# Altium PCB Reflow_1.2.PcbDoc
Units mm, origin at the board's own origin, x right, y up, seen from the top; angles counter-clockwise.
Board outline 49.5 x 49.5 mm, 2 copper layers (Top Layer, Bottom Layer); 51 components, 57 nets, 187 pads, 58 vias.
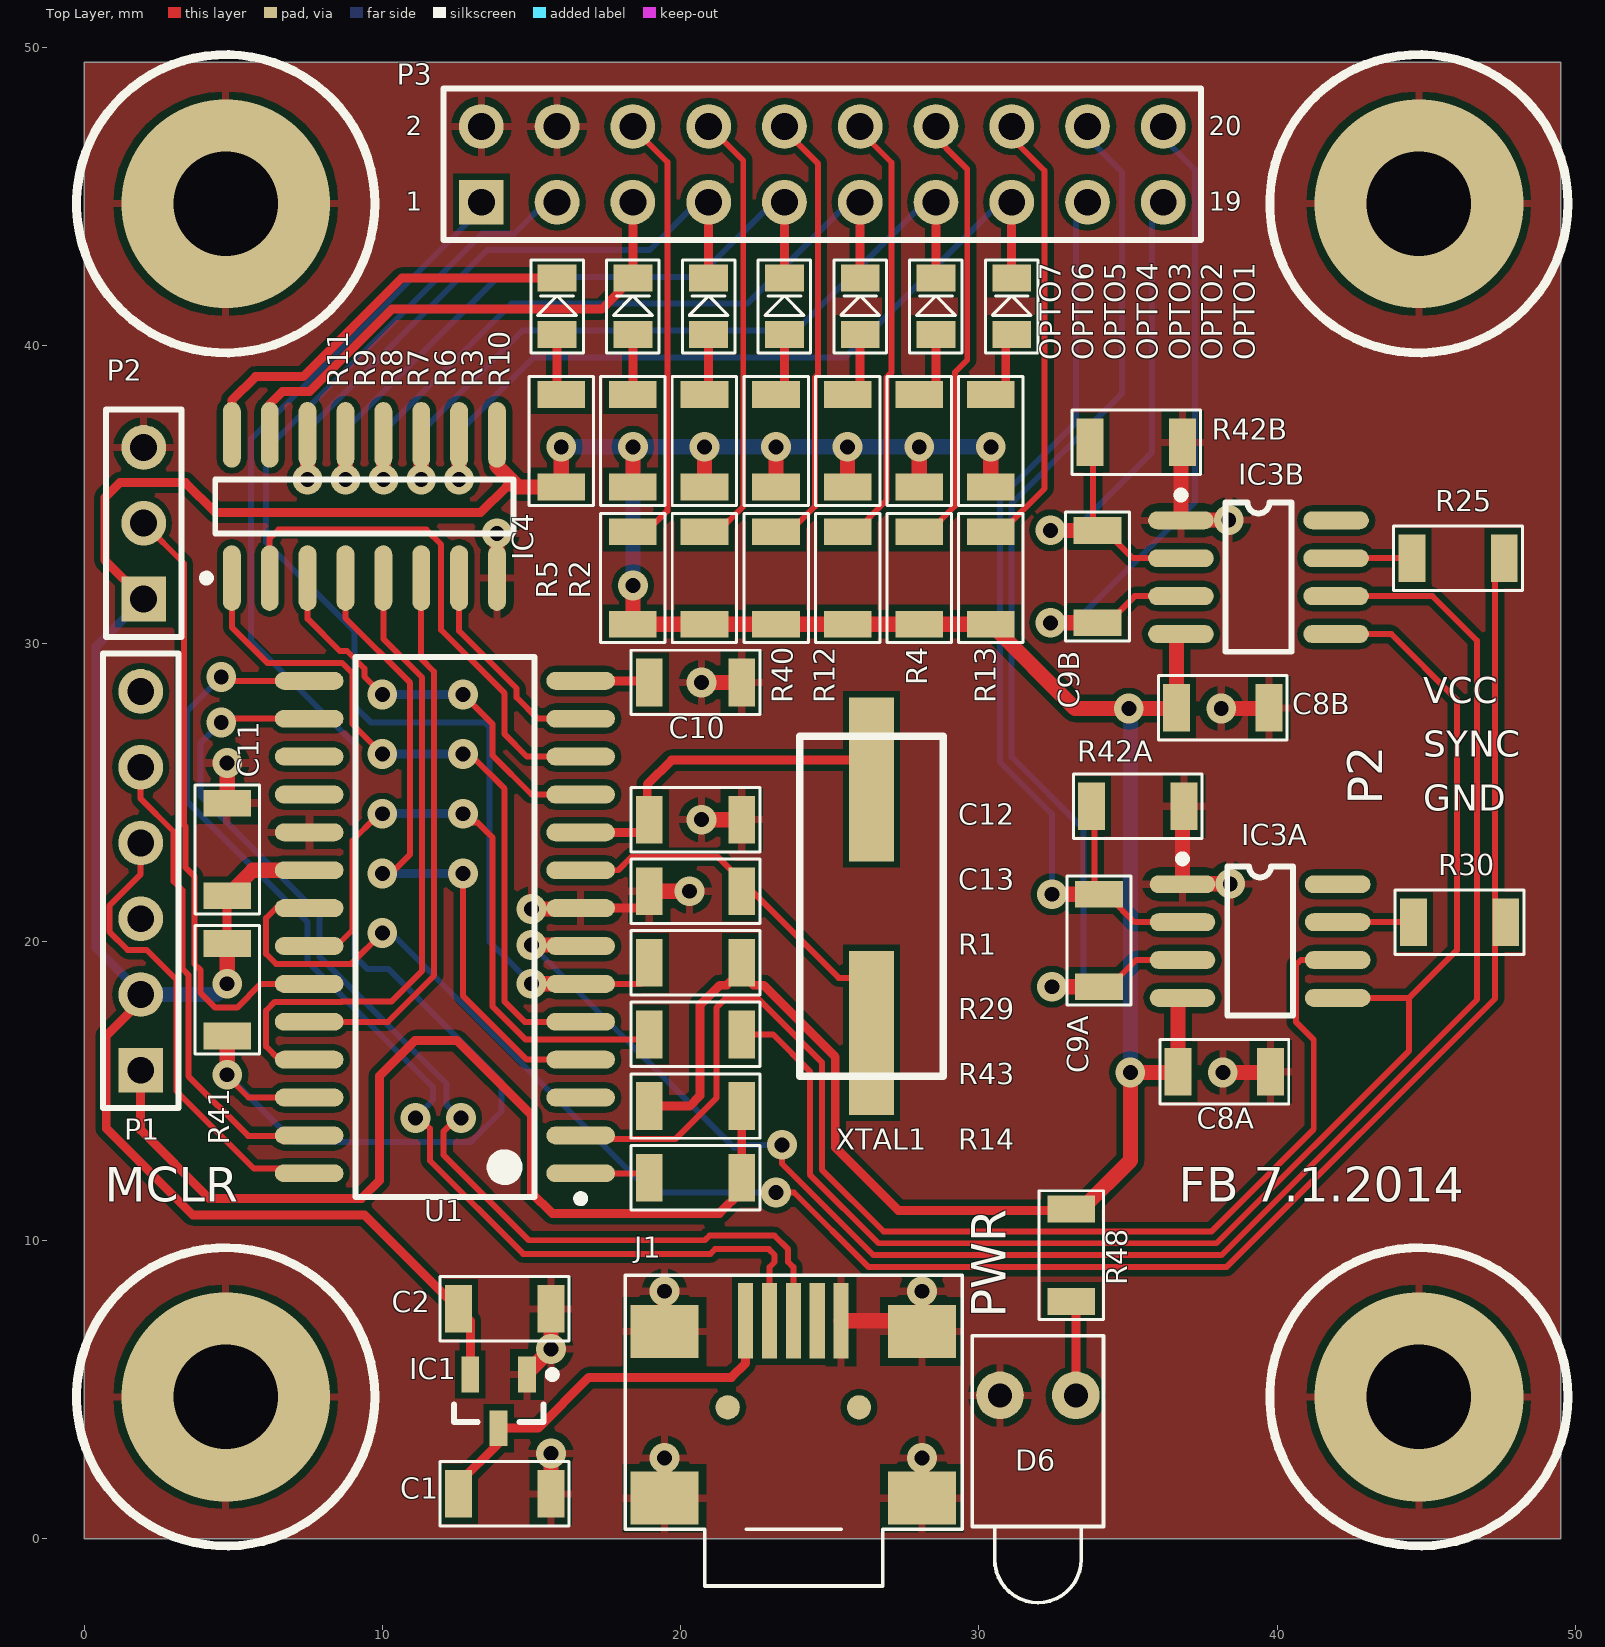
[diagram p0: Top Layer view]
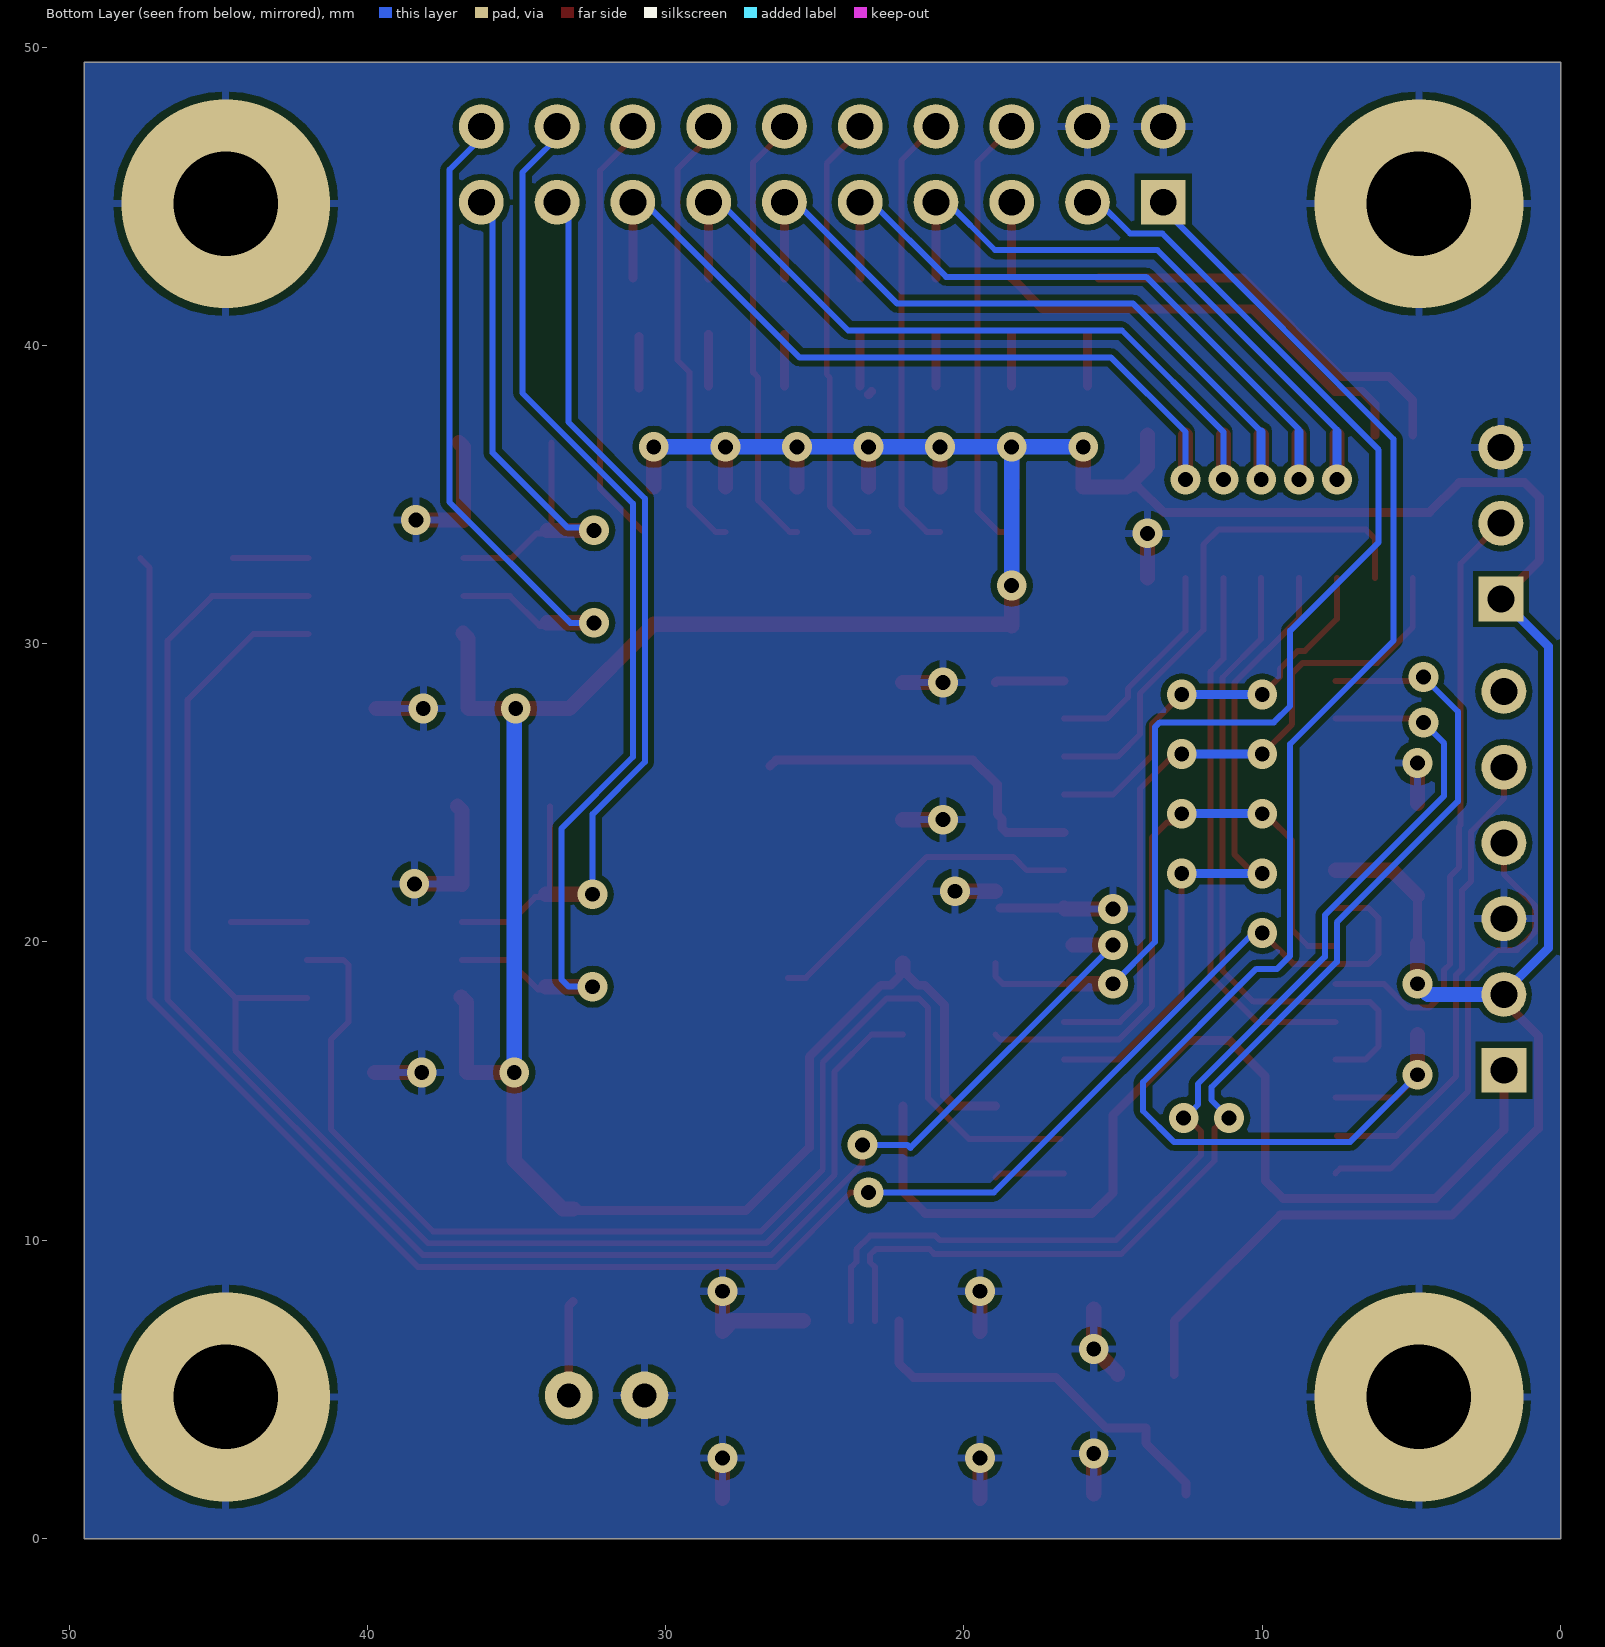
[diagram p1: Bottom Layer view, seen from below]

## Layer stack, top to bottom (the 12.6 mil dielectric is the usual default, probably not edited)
Top Solder: solder mask 0.0102, Solder Resist, Dk 3.5
Top Layer: signal copper 0.0356
Dielectric1: dielectric 0.32, FR-4, Dk 4.8
Bottom Layer: signal copper 0.0356
Bottom Solder: solder mask 0.0102, Solder Resist, Dk 3.5

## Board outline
0,0 0,49.5 49.5,49.5 49.5,0

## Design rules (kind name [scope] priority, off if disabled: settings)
Clearance [All] p1: gap=0.2
DiffPairsRouting [All] p1 off: maxlimit=0.254 minlimit=0.254 mostfreqgap=0.254 toplayer_minwidth=0.381 toplayer_maxwidth=0.381 toplayer_prefwidth=0.381 bottomlayer_minwidth=0.381 bottomlayer_maxwidth=0.381 bottomlayer_prefwidth=0.381 maxuncoupledlength=12.7
FabricationTestPointUsage [All] p1 off: valid=0 allowmultiple=FALSE
FabricationTestpoint [(IsPad And (OnTopLayer Or OnBottomLayer))] p1 off: side=3 testpointundercomponent=TRUE minsize=1.016 maxsize=2.54 preferedsize=1.524 minholesize=0 maxholesize=1.016 preferedholesize=0.813 testpointgrid=0.025 allowsidetop=TRUE allowsidebottom=TRUE usegrid=TRUE gridtolerance=0
FanoutControl Fanout_BGA [IsBGA] p1 off: bgadir=Out bgaviamode=Centered fanoutstyle=Auto fanoutdirection=Alternating viagrid=0.025 // Fanout_BGA (Default Rule)
FanoutControl Fanout_LCC [IsLCC] p2 off: bgadir=Out bgaviamode=Centered fanoutstyle=Auto fanoutdirection=Alternating viagrid=0.025 // Fanout_LCC (Default Rule)
FanoutControl Fanout_SOIC [IsSOIC] p3 off: bgadir=Out bgaviamode=Centered fanoutstyle=Auto fanoutdirection=Alternating viagrid=0.025 // Fanout_SOIC (Default Rule)
FanoutControl Fanout_Small [(CompPinCount < 5)] p4 off: bgadir=Out bgaviamode=Centered fanoutstyle=Auto fanoutdirection=OutThenIn viagrid=0.025 // Fanout_Small (Default Rule)
FanoutControl Fanout_Default [All] p5 off: bgadir=Out bgaviamode=Centered fanoutstyle=Auto fanoutdirection=Alternating viagrid=0.025 // Fanout_Default (Default Rule)
Height [All] p1 off: minheight=0 maxheight=25.4 prefheight=12.7
HoleSize [All] p1: absolutevalues=TRUE maxlimit=4.5 minlimit=0.025 maxpercent=80.000 minpercent=20.000
LayerPairs [All] p1 off: enforce=TRUE
MinimumSolderMaskSliver [All] p1 off: minsoldermaskwidth=0.254
PasteMaskExpansion [All] p1 off: expansion=0
PolygonConnect [All] p1: connectstyle=Relief reliefconductorwidth=0.254 reliefentries=4 polygonreliefangle="90 Angle" airgapwidth=0.254
RoomDefinition U_MAX66752 [InComponentClass('U_MAX66752')] p1: confinementstyle=ConfineIn formatcopy=TRUE lockcomponents=FALSE outline 46.026,38.825 30.975,38.825 30.975,26.025 46.026,26.025
RoomDefinition U_MAX66751 [InComponentClass('U_MAX66751')] p2: confinementstyle=ConfineIn formatcopy=TRUE lockcomponents=FALSE outline 46.077,26.625 31.026,26.625 31.026,13.825 46.077,13.825
RoutingLayers [All] p1 off: top layer_v5=TRUE bottom layer_v5=TRUE
RoutingPriority [All] p1 off: routingpriority=0
RoutingTopology [All] p1 off: topology=Shortest
RoutingVias [All] p1: holewidth=0.5 width=1 viastyle="Through Hole" minholewidth=0.4 minwidth=0.9 maxholewidth=5 maxwidth=10
SilkToSilkClearance [All] p1 off: silktosilkclearance=0.254
SilkToSolderMaskClearance SilkscreenOverComponentPads [IsPad] p1 off: minsilkscreentomaskgap=0.254 clearancetoexposedcopper=TRUE
SolderMaskExpansion [All] p1 off: expansion=0.102
UnpouredPolygon [All] p1: allowunpoured=FALSE
Width [All] p1: maxlimit=4 minlimit=0.2 preferedwidth=0.5
11 further rules are at their usual default settings.

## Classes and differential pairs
channel class MAX6675: U_MAX66751 U_MAX66752
component class "U_USB ESD EMV BUCHSE": J1
component class U_UNL2003_LED: IC4
component class U_PIC18F2550: C10 C11 C12 C13 P1 R14 U1 XTAL1
component class U_MAX66752: C8B C9B IC3B R42B
component class U_MAX66751: C8A C9A IC3A R42A
component class U_3V3_Regler: C1 C2 IC1
component class TOP_Sheet: D6 OPTO1 OPTO2 OPTO3 OPTO4 OPTO5 OPTO6 OPTO7 P2 P3 R1 R2 R3 R4 R5 R6 R7 R8 R9 R10 R11 R12 R13 R25 R29 R30 R40 R41 R43 R48
differential pair USB: +USB_P -USB_N

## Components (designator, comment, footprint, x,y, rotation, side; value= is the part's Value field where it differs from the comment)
C1 "1uF" RLCDT_1206 14.1,1.5 r0 top
C2 "1uF" RLCDT_1206 14.1,7.7 r0 top
C8A "100nF" RLCDT_1206 38.228,15.65 r0 top (schematic designator C8)
C8B "100nF" RLCDT_1206 38.177,27.85 r0 top (schematic designator C8)
C9A "100nF" RLCDT_1206 34.027,20.05 r90 top (schematic designator C9)
C9B "100nF" RLCDT_1206 33.976,32.25 r90 top (schematic designator C9)
C10 "220nF" RLCDT_1206 20.5,28.7 r0 top
C11 "100nF" RLCDT_1206 4.8,23.1 r90 top
C12 "22pF" RLCDT_1206 20.5,24.1 r180 top
C13 "22pF" RLCDT_1206 20.5,21.7 r0 top
D6 "LED1" LED-1 31.98,4.8 r270 top
IC1 "VRG_XC6206P332MR/SOT23" RLCDT_SOT23 13.9,4.6 r270 top
IC3A "IC_MAX6675" IC_SOIC150_8 39.426,20.03 r270 top (schematic designator IC3)
IC3B "IC_MAX6675" IC_SOIC150_8 39.375,32.23 r270 top (schematic designator IC3)
IC4 "ULN2003L" L16_N 9.4,34.6 r90 top
J1 "USB-MINI-B%C" USB-MINI-B_2 25.38,7.3 r180 top
OPTO1 "Value" OPTO_0805_POL 31.1,41.31 r90 top
OPTO2 "Value" OPTO_0805_POL 28.56,41.31 r90 top
OPTO3 "Value" OPTO_0805_POL 26.02,41.31 r90 top
OPTO4 "Value" OPTO_0805_POL 23.48,41.31 r90 top
OPTO5 "Value" OPTO_0805_POL 20.94,41.31 r90 top
OPTO6 "Value" OPTO_0805_POL 18.4,41.31 r90 top
OPTO7 "Value" OPTO_0805_POL 15.86,41.31 r90 top
P1 "Header 6" HDR1X6 1.9,15.7 r90 top
P2 "Header 3" HDR1X3 2,31.5 r90 top
P3 "Header 10X2" HDR2X10 13.32,44.8 r0 top
R1 "330R" RLCDT_1206 20.5,19.3 r0 top
R2 "330R" RLCDT_1206 20.8,32.2 r90 top
R3 "330R" RLCDT_1206 28,36.8 r270 top
R4 "330R" RLCDT_1206 28,32.2 r90 top
R5 "330R" RLCDT_1206 18.4,32.2 r90 top
R6 "330R" RLCDT_1206 25.6,36.8 r270 top
R7 "330R" RLCDT_1206 23.2,36.8 r270 top
R8 "330R" RLCDT_1206 20.8,36.8 r270 top
R9 "330R" RLCDT_1206 18.4,36.8 r270 top
R10 "330R" RLCDT_1206 30.4,36.8 r270 top
R11 "330R" RLCDT_1206 16,36.8 r270 top
R12 "330R" RLCDT_1206 25.6,32.2 r90 top
R13 "330R" RLCDT_1206 30.4,32.2 r90 top
R14 "470R" RLCDT_1206 20.5,12.1 r0 top
R25 "33R" RLCDT_1206 46.064,32.865 r180 top
R29 "33R" RLCDT_1206 20.5,16.9 r0 top
R30 "33R" RLCDT_1206 46.115,20.665 r180 top
R40 "330R" RLCDT_1206 23.2,32.2 r90 top
R41 "330R" RLCDT_1206 4.8,18.4 r90 top
R42A "0R" RLCDT_1206 35.327,24.55 r180 top (schematic designator R42)
R42B "0R" RLCDT_1206 35.276,36.75 r180 top (schematic designator R42)
R43 "4K7" RLCDT_1206 20.5,14.5 r180 top
R48 "330R" RLCDT_1206 33.1,9.5 r90 top
U1 "PIC18F2550-I/SO" SOIC-SO28_N 12.1,20.5 r180 top
XTAL1 "HCM49 4.000MABJ-UT" IC_M-HCM49 26.4,21.2 r90 top

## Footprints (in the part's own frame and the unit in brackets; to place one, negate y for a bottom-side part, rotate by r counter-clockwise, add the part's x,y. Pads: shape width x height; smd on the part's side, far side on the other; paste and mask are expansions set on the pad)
HDR1X3 [mm] "Connector; Header; 3 Position"
  rect 1.5x1.5 hole 0.9: 1(0,0)
  round 1.5 hole 0.9: 2(2.54,0) 3(5.08,0)
  silkscreen extent -1.27,-1.27 6.35,1.27
HDR1X6 [mm] "Connector; Header; 6 Position"
  rect 1.5x1.5 hole 0.9: 1(0,0)
  round 1.5 hole 0.9: 2(2.54,0) 3(5.08,0) 4(7.62,0) 5(10.16,0) 6(12.7,0)
  silkscreen extent -1.27,-1.27 13.97,1.27
HDR2X10 [mm] "Connector; Header; 10x2 Position"
  rect 1.5x1.5 hole 0.9: 1(0,0)
  round 1.5 hole 0.9: 2(0,2.54) 3(2.54,0) 4(2.54,2.54) 5(5.08,0) 6(5.08,2.54) 7(7.62,0) 8(7.62,2.54) 9(10.16,0) 10(10.16,2.54) 11(12.7,0) 12(12.7,2.54) 13(15.24,0) 14(15.24,2.54) 15(17.78,0) 16(17.78,2.54) 17(20.32,0) 18(20.32,2.54) 19(22.86,0) 20(22.86,2.54)
  silkscreen extent -1.27,-1.27 24.13,3.81
IC_M-HCM49 [mm] "Quarz 25MHz"
  rect 5.5x1.5 smd: 1(-4.25,0) 2(4.25,0)
  silkscreen extent -5.7,-2.4 5.7,2.4, body extent -5.7,-2.4 5.7,2.4, height 4.4
IC_SOIC150_8 [mm] "SOIC, 1.27mm, 150mil body"
  oval 0.6x2.2 smd: 1(-1.905,-2.6) 2(-0.635,-2.6) 3(0.635,-2.6) 4(1.905,-2.6) 5(1.905,2.6) 6(0.635,2.6) 7(-0.635,2.6) 8(-1.905,2.6)
  silkscreen extent -2.88,-2.72 2.5,1.1, body extent -2.67,-1.95 2.67,1.95, height 1.75
L16_N [mm] "SOIC, 16-Leads, Body 9.9x3.9mm, Pitch 1.27mm, IPC Medium Density"
  oval 2.2x0.6 smd: 1(-2.4,4.445) 2(-2.4,3.175) 3(-2.4,1.905) 4(-2.4,0.635) 5(-2.4,-0.635) 6(-2.4,-1.905) 7(-2.4,-3.175) 8(-2.4,-4.445) 9(2.4,-4.445) 10(2.4,-3.175) 11(2.4,-1.905) 12(2.4,-0.635) 13(2.4,0.635) 14(2.4,1.905) 15(2.4,3.175) 16(2.4,4.445)
  silkscreen extent -2.52,-5 0.9,5.42, body extent -1.95,-4.95 1.95,4.95, height 1.75
LED-1 [mm] "LED; 2 Leads"
  round 1.6 hole 0.8: 1(0,1.27) 2(0,-1.27)
  silkscreen extent -2,-2.2 6.95,2.2, body extent -0.71,-2 6.99,2, height 6.2
OPTO_0805_POL [mm] "Chip Resistor; Body 2.0 x 1.3 mm (LxW typ)"
  rect 0.9x1.3 smd: A(-0.95,0) K(0.95,0)
  silkscreen extent -1.56,-0.88 1.56,0.88, body extent -1,-0.65 1,0.65, height 1.35
RLCDT_1206 [mm] "Chip Resistor; Body 3.2 x 1.6 mm (LxW typ)"
  rect 0.9x1.6 smd: 1(-1.55,0) 2(1.55,0)
  silkscreen extent -2.16,-1.08 2.16,1.08, body extent -1.6,-0.8 1.6,0.8, height 1.25
RLCDT_SOT23 [mm] "SOT23 Gehäuse"
  rect 1.2x0.6 smd: 1(-0.9,0.95) 2(-0.9,-0.95) 3(0.9,0)
  silkscreen extent -1.02,-1.5 0.7,1.93, body extent -0.7,-1.5 0.7,1.5, height 1.1
SOIC-SO28_N [mm] "SOIC, 28-Leads, Body 17.9x7.5mm, Pitch 1.27mm, IPC Medium Density"
  oval 2.3x0.6 smd: 1(-4.55,8.255) 2(-4.55,6.985) 3(-4.55,5.715) 4(-4.55,4.445) 5(-4.55,3.175) 6(-4.55,1.905) 7(-4.55,0.635) 8(-4.55,-0.635) 9(-4.55,-1.905) 10(-4.55,-3.175) 11(-4.55,-4.445) 12(-4.55,-5.715) 13(-4.55,-6.985) 14(-4.55,-8.255) 15(4.55,-8.255) 16(4.55,-6.985) 17(4.55,-5.715) 18(4.55,-4.445) 19(4.55,-3.175) 20(4.55,-1.905) 21(4.55,-0.635) 22(4.55,0.635) 23(4.55,1.905) 24(4.55,3.175) 25(4.55,4.445) 26(4.55,5.715) 27(4.55,6.985) 28(4.55,8.255)
  silkscreen extent -4.67,-9.05 3,9.23, body extent -3.8,-9.06 3.8,9.06, height 2.65
USB-MINI-B_2 [mil]
  rect 20x100 smd: 1(0,0) 2(31.5,0) 3(62.99,0) 4(94.49,0) 5(125.98,0)
  rect 90x70 smd: 6(-106.99,234.17) 7(-106.99,14.17) 8(233.01,14.17) 9(233.01,234.17)
  round 32 smd: ""(-23.62,114.17) ""(149.61,114.17)
  silkscreen extent -160,-60 285,350, body extent -133,-45 261,305, height 157

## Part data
C1 C2 C8A C8B C9A C9B C10 C11 C12 C13: library part C_KERAMIK, "Kondensator, Keramik"
D6: "Typical RED GaAs LED"
IC1: "VOLTAGE REGULATOR 3V3 250mA"
IC4: "High-Voltage, High-Current Darlington Array"
OPTO1 OPTO2 OPTO3 OPTO4 OPTO5 OPTO6 OPTO7: library part OPTO_LED_KP-2012MGC, "LED, 0805, mega green"
P1: "Header, 6-Pin"
P2: "Header, 3-Pin"
P3: "Header, 10-Pin, Dual row"
R1 R2 R3 R4 R5 R6 R7 R8 R9 R10 R11 R12 R13 R14 R25 R29 R30 R40 R41 R42A R42B R43 R48: library part R, "Widerstand"
U1: "High Performance, Enhanced Flash, USB Microcontroller with nanoWatt Technology, 32K Flash, 28-Pin SOIC, Industrial Temperature Range"
XTAL1: library part IC_XTAL_4MHz, "Quarz 4MHz"

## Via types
v1: diameter 1, hole 0.5, Top Layer to Bottom Layer, 54 vias
v2: diameter 7, hole 3.5, Top Layer to Bottom Layer, 4 vias

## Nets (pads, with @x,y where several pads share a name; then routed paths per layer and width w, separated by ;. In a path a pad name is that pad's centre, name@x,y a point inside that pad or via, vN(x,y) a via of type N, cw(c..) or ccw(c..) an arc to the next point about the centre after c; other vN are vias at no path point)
3V3: C2.1 C8A.1 C8B.1 C11.1 IC1.2 IC3A.4 IC3B.4 IC4.9 P1.2 P2.1 R1.2 R2.1 R3.2 R4.1 R5.1 R6.2 R7.2 R8.2 R9.2 R10.2 R11.2 R12.1 R13.1 R40.1 R41.2 R43.2 R48.2 U1.20 | length 164.1
  Top Layer w0.3: P1.2@1.9,17.8 P1.2@1.9,18.008 ; P1.2@1.9,18.3 P1.2 P1.2@1.9,18.008 ; P2.1 0.7,32.8 0.7,34.9 1.2,35.4 3.4,35.4 4.4,34.4 13.3,34.4 14.15,35.25 14.55,35.25 ; R41.2 C11.1 ; IC1.2 12.95,7.3 C2.1 9.404,10.846 3.654,10.846 0.746,13.754 0.746,16.854 P1.2@1.9,18.008 ; R43.2 20.3,14.5 20.65,14.85 20.65,17.886 21.314,18.55 21.55,18.55 R1.2@22.05,19.05 ; R1.2@22.2,18.8 22.45,18.55 22.786,18.55 25.185,16.151 25.185,13.115 27.3,11 32.9,11 R48.2@33.025,11.125
  Top Layer w0.508: v1(4.8,18.6) R41.2 ; C11.1 5.655,22.405 U1.20 ; IC4.9 13.845,35.955 14.55,35.25 R11.2 v1(16,36.6) ; R5.1@18.4,30.6 v1(18.4,31.95) ; R5.1 R2.1 R40.1 R12.1 R4.1 R13.1 33.225,27.825 v1(35.026,27.825) C8B.1@36.602,27.825 ; R9.2 v1(18.4,36.6) ; R8.2 v1(20.8,36.6) ; R1.2@22.05,19.05 R1.2 ; R7.2 v1(23.2,36.6) ; R6.2 v1(25.6,36.6) ; R3.2 v1(28,36.6) ; R10.2 v1(30.4,36.6) ; R48.2 33.45,11.05 35.077,12.677 v1(35.077,15.625) C8A.1@36.653,15.625 ; C8B.1 36.627,30.177 IC3B.4 IC3B.4@36.8,30.35 ; C8A.1 36.678,17.977 IC3A.4 IC3A.4@36.851,18.15
  Bottom Layer w0.3: P2.1@1.8,31.3 0.4,29.9 0.4,19.8 P1.2@1.9,18.3
  Bottom Layer w0.508: P1.2 4.44,18.24 v1(4.8,18.6) ; v1(16,36.6) v1(18.4,36.6) v1(20.8,36.6) v1(23.2,36.6) v1(25.6,36.6) v1(28,36.6) v1(30.4,36.6) ; v1(18.4,31.95) v1@18.4,36.55 ; v1(35.026,27.825) 35.077,27.774 v1(35.077,15.625)
5V: C1.1 IC1.3 J1.5 | length 13.4
  Top Layer w0.3: C1.1 12.55,1.85 13.9,3.2 IC1.3 15.222,3.7 16.922,5.4 21.7,5.4 22.18,5.88 J1.5
CS2: IC3A.6 U1.2 | length 42.2
  Top Layer w0.2: U1.2@16.765,13.4 19.836,13.4 21.2,14.764 21.2,17.8 21.5,18.1 22.6,18.1 24.735,15.965 24.735,12.365 26.8,10.3 37.801,10.3 41.226,13.725 41.226,16.725 40.626,17.325 40.626,19.226 40.795,19.395 IC3A.6
FTDI_RXD: U1.17
FTDI_TXD: U1.18
GND: C1.2 C2.2 C8A.2 C8B.2 C10.2 C11.2 C12.1 C13.1 D6.2 IC1.1 IC3A.1 IC3B.1 IC4.8 J1.1 J1.6 J1.7 J1.8 J1.9 P1.3 P2.3 P3.2 P3.4 R42A.1 R42B.1 U1.8 U1.19 | length 34.3
  Top Layer w0.3: U1.8 C13.1@18.8,21.135
  Top Layer w0.508: C11.2 v1(4.8,26) ; IC4.8 v1@13.845,33.55 ; IC1.1 14.85,5.55 v1(15.65,6.35) C2.2 ; v1@15.1,21.1 16.615,21.1 U1.8 ; C1.2 v1(15.65,2.85) ; C13.1 v1(20.3,21.7) ; J1.9 v1(19.461,2.702) ; J1.8 v1(19.461,8.29) ; v1(20.7,24.1) C12.1 ; v1(20.7,28.7) C10.2 ; J1.1 27.738,7.3 J1.7 v1(28.097,8.29) ; J1.6 v1(28.097,2.702) ; R42B.1@36.926,36.75 36.775,36.599 IC3B.1 36.79,34.15 v1(38.376,34.15) ; R42A.1@36.977,24.55 36.826,24.399 IC3A.1 36.841,21.95 v1(38.427,21.95) ; v1(38.126,27.825) C8B.2@39.702,27.825 ; v1(38.177,15.625) C8A.2@39.753,15.625
  other v1: 15,21.1 13.845,33.7
  other v2: 4.75,4.75 44.75,4.75 4.75,44.75 44.75,44.75
MCLR: P1.1 R14.2 R43.1 | length 34.4
  Top Layer w0.3: P1.1 1.9,13.7 4.2,11.4 9.3,11.4 9.9,12 9.9,15.5 11.1,16.7 12.5,16.7 15,14.2 15,11.6 15.7,10.9 21.3,10.9 22.05,11.65 R14.2 R43.1
NetC10_1: C10.1 U1.14 | length 2.3
  Top Layer w0.3: U1.14 18.895,28.755 C10.1
NetD6_1: D6.1 R48.1 | length 3.2
  Top Layer w0.3: R48.1 33.25,7.8 D6.1
NetIC3A_5: IC3A.5 IC3B.5 R29.2 | length 49.8
  Top Layer w0.2: R29.2 23.1,16.9 24.335,15.665 24.335,12.199 26.634,9.9 37.967,9.9 44.425,16.358 44.425,18.125 ; IC3B.5 43.826,30.325 46.026,28.125 46.026,19.726 44.425,18.125 ; IC3A.5 44.425,18.125
NetIC3A_7: IC3A.7 R30.2 | length 2.5
  Top Layer w0.2: IC3A.7 R30.2
NetIC3B_6: IC3B.6 U1.7 | length 58.7
  Top Layer w0.2: v1(23.4,13.2) 23.4,12.569 26.469,9.5 38.132,9.5 46.7,18.068 46.7,30.1 45.205,31.595 IC3B.6
  Top Layer w0.508: v1(15,19.9) U1.7@16.35,19.9
  Bottom Layer w0.2: v1(15,19.9) 21.8,13.1 21.9,13.2 v1(23.4,13.2)
NetIC3B_7: IC3B.7 R25.2 | length 2.5
  Top Layer w0.2: IC3B.7 R25.2
NetIC4_1: IC4.1 U1.5 | length 24
  Top Layer w0.2: IC4.1 4.955,30.545 6.145,29.355 8.649,29.355 9,29.004 9,27.3 v1(10,26.3) ; v1@12.7,26.2 13.033,26.2 14.1,25.133 14.1,18 14.775,17.325 U1.5
  Bottom Layer w0.3: v1(10,26.3) v1(12.7,26.3)
NetIC4_2: IC4.2 U1.12 | length 17.5
  Top Layer w0.2: IC4.2 6.225,33.525 6.525,33.825 11.475,33.825 11.975,33.325 11.975,30.459 14.1,28.334 14.1,26.966 14.851,26.215 U1.12
NetIC4_3: IC4.3 U1.11 | length 13.7
  Top Layer w0.2: IC4.3 7.495,30.834 8.574,29.755 8.814,29.755 9.4,29.169 9.4,28.9 v1(10,28.3) ; v1(12.7,28.3) 13.7,27.3 13.7,26.245 15,24.945 U1.11
  Bottom Layer w0.3: v1(10,28.3) v1(12.7,28.3)
NetIC4_4: IC4.4 U1.4 | length 23.1
  Top Layer w0.2: IC4.4 8.765,30.857 10.935,28.687 10.935,22.935 10.3,22.3 v1(10,22.3) ; v1@12.5,22.3 12.7,22.1 12.7,18.2 14.845,16.055 U1.4
  Bottom Layer w0.3: v1(10,22.3) v1(12.7,22.3)
NetIC4_5: IC4.5 U1.25 | length 22.3
  Top Layer w0.2: U1.25 6.545,16.055 6.1,16.5 6.1,17.7 6.395,17.995 8.649,17.995 8.654,18 10.3,18 11.335,19.035 11.335,28.865 10.035,30.165 IC4.5
NetIC4_6: IC4.6 U1.24 | length 18.3
  Top Layer w0.2: U1.24 10.191,17.325 11.735,18.869 11.735,29.065 11.305,29.495 IC4.6
NetIC4_7: IC4.7 U1.13 | length 7.2
  Top Layer w0.2: IC4.7 12.575,30.425 14.5,28.5 14.5,28.2 15.215,27.485 U1.13
NetOPTO1_A: OPTO1.A R10.1 | length 1.7
  Top Layer w0.3: R10.1@30.9,38.57 OPTO1.A@30.9,40.3
NetOPTO2_A: OPTO2.A R3.1 | length 1.7
  Top Layer w0.3: R3.1@28.56,38.63 OPTO2.A
NetOPTO3_A: OPTO3.A R6.1 | length 1.7
  Top Layer w0.3: R6.1@26.02,38.63 OPTO3.A
NetOPTO4_A: OPTO4.A R7.1 | length 1.9
  Top Layer w0.3: R7.1@23.1,38.45 R7.1 ; R7.1@23.48,38.63 OPTO4.A
NetOPTO5_A: OPTO5.A R8.1 | length 1.7
  Top Layer w0.3: R8.1@20.94,38.63 OPTO5.A
NetOPTO6_A: OPTO6.A R9.1 | length 1.7
  Top Layer w0.3: R9.1@18.4,38.63 OPTO6.A
NetOPTO7_A: OPTO7.A R11.1 | length 1.7
  Top Layer w0.3: R11.1@15.86,38.63 OPTO7.A
NetP2_2: P2.2 U1.23 | length 20.7
  Top Layer w0.2: P2.2 3.35,32.69 3.35,23.921 3.4,23.871 3.4,22.5 3.7,22.2 3.7,22.124 3.7,19.263 3.9,19.063 3.9,18.3 4.4,17.8 5.131,17.8 5.926,18.595 U1.23
NetP3_1: P3.1 R41.1 U1.26 | length 53.7
  Top Layer w0.2: R41.1 4.8,15.5 5.515,14.785 U1.26
  Top Layer w0.508: v1(4.8,15.55) R41.1@4.8,16.9
  Bottom Layer w0.2: v1(4.8,15.55) 7.05,13.3 12.966,13.3 14,14.334 14,15.3 10.2,19.1 9.5,19.1 9.065,19.535 9.065,26.635 5.6,30.1 5.6,36.858 12.94,44.198 P3.1@12.94,44.8
NetP3_3: P3.3 R1.1 U1.6 | length 40.8
  Top Layer w0.2: U1.6 18.695,18.595 18.95,18.85 R1.1
  Top Layer w0.508: v1(15,18.6) U1.6@16.35,18.6
  Bottom Layer w0.2: v1(15,18.6) 13.6,20 13.6,27.2 13.435,27.365 9.613,27.365 9.065,27.913 9.065,30.435 6.1,33.4 6.1,36.5 13.35,43.75 14.43,43.75 P3.3@15.48,44.8
NetP3_6: P3.6 R5.2 | length 15.2
  Top Layer w0.2: P3.6@18.02,47.34 18.36,47.34 19.554,46.146 19.554,34.454 18.85,33.75 R5.2
NetP3_8: P3.8 R2.2 | length 15.3
  Top Layer w0.2: P3.8@20.56,47.34 20.96,47.34 22.1,46.2 22.1,34.6 21.25,33.75 R2.2
NetP3_10: P3.10 R40.2 | length 15.2
  Top Layer w0.2: P3.10@23.1,47.34 23.36,47.34 24.6,46.1 24.6,39.024 24.5,38.924 24.5,34.6 23.65,33.75 R40.2
NetP3_12: P3.12 R12.2 | length 15.1
  Top Layer w0.2: R12.2 25.851,33.75 26.9,34.799 26.9,38.924 27.07,39.094 27.07,46.13 25.86,47.34 P3.12@25.64,47.34
NetP3_14: P3.14 R4.2 | length 15
  Top Layer w0.2: R4.2 28.33,33.75 29.2,34.62 29.2,39.1 29.61,39.51 29.61,45.91 P3.14@28.18,47.34
NetP3_16: P3.16 R13.2 | length 14.7
  Top Layer w0.2: P3.16@30.72,47.34 32.2,45.86 32.2,35.2 R13.2@30.8,33.8
NetR25_1: R25.1 R30.1 U1.21 | length 67.8
  Top Layer w0.2: U1.21 6.435,21.135 6.1,20.8 6.1,19.6 6.435,19.265 8.965,19.265 v1(10,20.3) ; v1(23.2,11.6) 23.803,11.6 26.303,9.1 38.298,9.1 47.3,18.102 47.3,32.551 R25.1
  Bottom Layer w0.2: v1(10,20.3) 10.3,20.3 19,11.6 v1(23.2,11.6)
NetR29_1: R29.1 U1.22 | length 21.4
  Top Layer w0.2: U1.22 8.465,19.865 9,20.4 9,23.4 v1@9.8,24.2 ; v1@12.5,24 13.2,24 13.7,23.5 13.7,17.834 14.809,16.725 18.775,16.725 R29.1
  Bottom Layer w0.3: v1(10,24.3) v1(12.7,24.3)
NetU1_3: U1.3
OUT1: IC4.10 OPTO1.K P3.15 | length 26.7
  Top Layer w0.3: OPTO1.K P3.15
  Top Layer w0.508: v1@12.575,35.65 IC4.10
  Bottom Layer w0.2: v1@12.575,35.65 12.575,37.1 15.075,39.6 25.52,39.6 P3.15@30.72,44.8
  other v1: 12.575,35.5
OUT2: IC4.11 OPTO2.K P3.13 | length 25.4
  Top Layer w0.3: OPTO2.K P3.13
  Top Layer w0.508: v1@11.305,35.65 IC4.11
  Bottom Layer w0.2: v1@11.305,35.65 11.305,37.103 14.702,40.5 23.88,40.5 P3.13@28.18,44.8
  other v1: 11.305,35.5
OUT3: IC4.12 OPTO3.K P3.11 | length 24.1
  Top Layer w0.3: OPTO3.K P3.11
  Top Layer w0.508: v1@10.035,35.65 IC4.12
  Bottom Layer w0.2: 10.035,37.1 10.035,37.106 14.329,41.4 22.24,41.4 P3.11@25.64,44.8
  Bottom Layer w0.3: v1@10.035,35.65 10.035,37.1
  other v1: 10.035,35.5
OUT4: IC4.13 OPTO4.K P3.9 | length 22.9
  Top Layer w0.3: OPTO4.K P3.9
  Top Layer w0.508: v1@8.765,35.65 IC4.13
  Bottom Layer w0.2: 8.765,37.1 8.765,37.174 13.891,42.3 20.6,42.3 P3.9@23.1,44.8
  Bottom Layer w0.3: v1@8.765,35.65 8.765,37.1
  other v1: 8.765,35.5
OUT5: IC4.14 OPTO5.K P3.7 | length 21.6
  Top Layer w0.3: OPTO5.K P3.7
  Top Layer w0.508: v1@7.495,35.65 IC4.14
  Bottom Layer w0.2: 7.495,37.1 7.495,37.176 13.519,43.2 18.96,43.2 P3.7@20.56,44.8
  Bottom Layer w0.3: v1@7.495,35.65 7.495,37.1
  other v1: 7.495,35.5
OUT6: IC4.15 OPTO6.K P3.5 | length 17.5
  Top Layer w0.3: IC4.15 6.225,38.025 6.65,38.45 7.557,38.45 10.321,41.214 17.354,41.214 OPTO6.K P3.5
OUT7: IC4.16 OPTO7.K | length 13.4
  Top Layer w0.3: IC4.16 4.955,38.155 5.75,38.95 7.35,38.95 10.66,42.26 OPTO7.K@15.48,42.26
PGC: P1.5 U1.27 | length 15.9
  Top Layer w0.2: P1.5 1.9,24.805 3,23.705 3,22.034 3.3,21.734 3.3,19.097 3.5,18.897 3.5,15.5 5.5,13.5 U1.27@7.5,13.5
PGD: P1.4 U1.28 | length 15.7
  Top Layer w0.2: P1.4 1.9,22.265 0.85,21.215 0.85,20.345 1.465,19.73 2.101,19.73 3.1,18.731 3.1,15 5.7,12.4 7.395,12.4 U1.28
T+1: C9B.1 IC3B.3 P3.20 | length 24.5
  Top Layer w0.2: C9B.1@33.976,30.6 34.226,30.6 35.221,31.595 IC3B.3
  Top Layer w0.508: v1(32.4,30.7) C9B.1
  Bottom Layer w0.2: v1(32.4,30.7) 33.199,30.7 37.246,34.747 37.246,45.894 P3.20@35.8,47.34
T+2: C9A.1 IC3A.3 P3.18 | length 37.7
  Top Layer w0.2: C9A.1@34.027,18.4 34.277,18.4 35.272,19.395 IC3A.3
  Top Layer w0.508: v1(32.451,18.5) C9A.1
  Bottom Layer w0.2: v1(32.451,18.5) 33.25,18.5 33.5,18.75 33.5,23.8 31.1,26.2 31.1,34.7 34.8,38.4 34.8,45.8 P3.18@33.26,47.34
T-1: C9B.2 IC3B.2 P3.19 R42B.2 | length 20.9
  Top Layer w0.2: R42B.2@33.826,36.75 33.826,33.85 33.876,33.8 33.976,33.7 34.326,33.7 35.161,32.865 IC3B.2
  Top Layer w0.508: v1(32.4,33.8) 33.876,33.8 C9B.2
  Bottom Layer w0.2: v1@32.2,33.9 33.299,33.9 35.8,36.401 P3.19@35.8,44.8
T-2: C9A.2 IC3A.2 P3.17 R42A.2 | length 32.8
  Top Layer w0.2: R42A.2@33.877,24.55 33.877,21.65 34.027,21.5 34.377,21.5 35.212,20.665 IC3A.2
  Top Layer w0.508: v1(32.451,21.6) C9A.2
  Bottom Layer w0.2: v1(32.451,21.6) 32.451,24.283 30.7,26.034 30.7,34.866 33.26,37.426 P3.17@33.26,44.8
TO_MCLR: R14.1 U1.1 | length 2.4
  Top Layer w0.2: U1.1 18.805,12.245 R14.1
TO_OSC1: C13.2 U1.9 XTAL1.1 | length 11.1
  Top Layer w0.2: U1.9 17.904,22.405 18.353,22.854 21.246,22.854 25.3,18.8 XTAL1.1@25.9,18.8
TO_OSC2: C12.2 U1.10 XTAL1.2 | length 11.7
  Top Layer w0.3: U1.10 18.578,23.675 18.73,23.827 18.73,24.13 18.881,24.281 18.881,25.281 19.7,26.1 26.3,26.1 XTAL1.2@26.5,25.9
USB_N: J1.4 U1.15 | length 38.9
  Top Layer w0.2: v1(4.6,28.882) 4.727,28.755 U1.15 ; v1(11.111,14.1) 11.246,14.1 11.6,13.746 11.6,12.666 14.72,9.546 21.001,9.546 21.155,9.7 22.958,9.7 23.153,9.505 23.153,9.273 22.98,9.1 J1.4
  Bottom Layer w0.2: v1(4.6,28.882) 3.446,27.728 3.446,24.712 7.5,20.658 7.5,19.334 11.7,15.134 11.7,14.7 v1@11.1,14.1
USB_P: J1.3 U1.16 | length 37.2
  Top Layer w0.2: v1(4.6,27.358) 4.727,27.485 U1.16 ; v1(12.635,14.1) 12.5,14.1 12.054,13.654 12.054,12.854 14.908,10 20.813,10 20.967,10.154 23.146,10.154 23.607,9.693 23.607,9.273 23.78,9.1 J1.3
  Bottom Layer w0.2: v1(4.6,27.358) 3.9,26.658 3.9,24.9 7.9,20.9 7.9,19.5 12.154,15.246 12.154,14.546 v1@12.6,14.1
pads on no net: IC3A.8 IC3B.8 J1. J1.2 P1.6

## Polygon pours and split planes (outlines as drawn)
GND on Bottom Layer "BOT GND" (solid, remove dead copper, pour order 5): 0,0 0,49.5 49.5,49.5 49.5,0
GND on Top Layer "BOT GND" (solid, remove dead copper, pour order 4): 0,0 0,49.5 49.5,49.5 49.5,0

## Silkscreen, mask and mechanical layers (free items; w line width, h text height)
Top Overlay:
  circle w0.3: c44.75,4.75 r5
  circle w0.3: c4.75,4.75 r5
  circle w0.3: c44.75,44.75 r5
  circle w0.3: c4.75,44.75 r5
  text "Reflow-Controller V1.2" at 1.9,51.1 h5
  text "VCC" at 44.9,27.7 h1.5
  text "SYNC" at 44.9,25.9 h1.5
  text "P2" at 43.9,24.6 h2 r90
  text "GND" at 44.9,24.1 h1.5
  text "MCLR" at 0.7,10.9 h2
  text "FB 7.1.2014" at 36.7,10.9 h2
  text "PWR" at 31.28,7.4 h2 r90
Mechanical 1:
  the board outline again, w0.2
